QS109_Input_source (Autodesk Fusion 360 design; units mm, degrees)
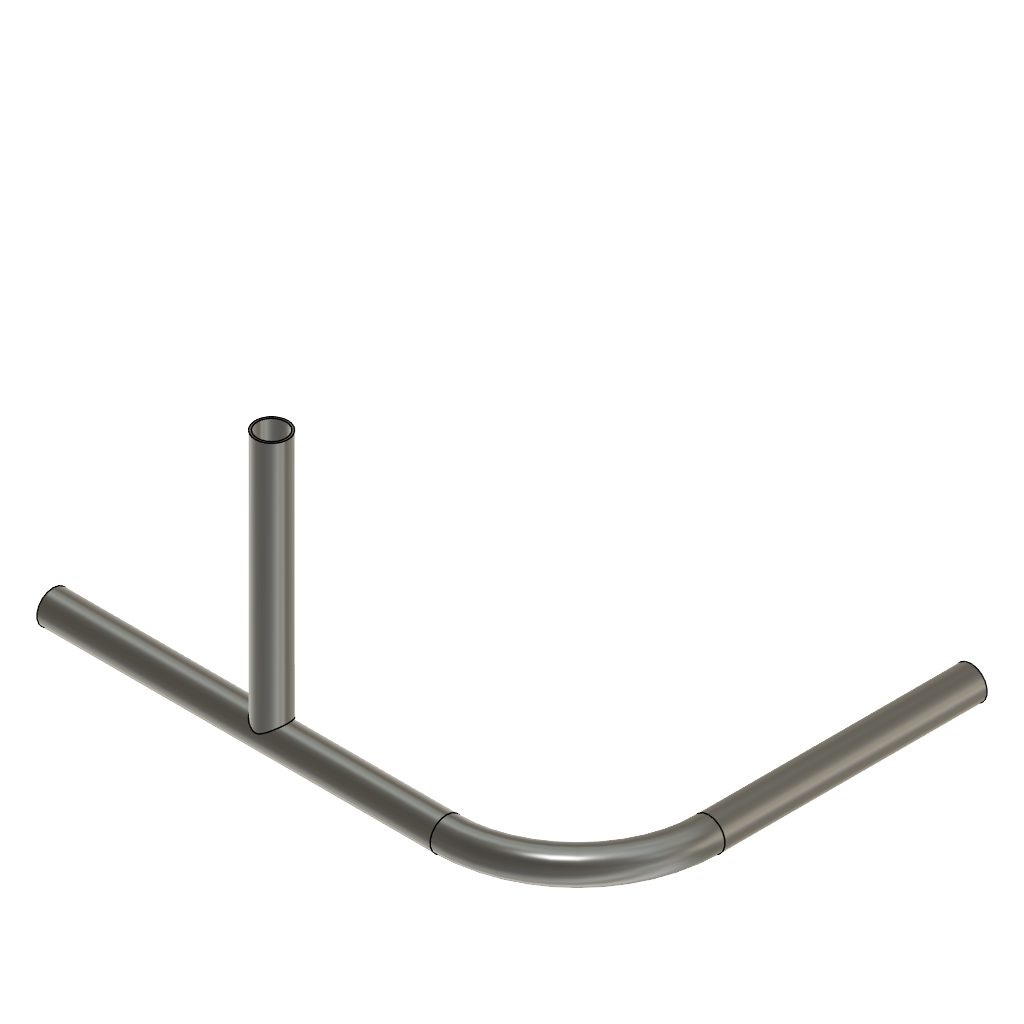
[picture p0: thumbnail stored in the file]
part number: 2026-10-26-11-38-19-526
sketch "tube H1 Bent host" plane through (0, 0, 0) normal (0, 0, 1) x axis (1, 0, 0)
  line L1 (457.2, 0) -> (0, 0)
  line L2 (609.6, 457.2) -> (609.6, 152.4)
  arc A1 centre (457.2, 152.4) radius 152.4 clockwise from (609.6, 152.4) to (457.2, 0)
work_plane "WorkPlane1" ExtraOffset 0
sketch "Sketch2" plane through (0, 0, 0) normal (1, 0, 0) x axis (0, 0, 1)
  circle C1 centre (0, 0) radius 19.05
  circle C2 centre (0, 0) radius 16.637
sweep "Sweep1" sketch "Sketch2" TwistAngle 0 TaperAngle 0 bodies "H1 Bent host"
sketch "tube I1 Imported coped brace" plane through (0, 0, 0) normal (0, 0, 1) x axis (1, 0, 0)
work_plane "WorkPlane2" ExtraOffset 0
sketch "Sketch4" plane through (254, 0, 0) normal (0, 0, 1) x axis (0, 1, 0)
  circle C1 centre (0, 0) radius 19.05
  circle C2 centre (0, 0) radius 16.637
sweep "Sweep2" sketch "Sketch4" TwistAngle 0 TaperAngle 0 bodies "I1 Imported coped brace"
base_feature "Base Feature"
surface_stitch "SurfaceStitch1" StitchingTolerence 0.01 bodies "normcope_I1_Imported_coped_brace_A"
split "Split1" bodies "I1 Imported coped brace"
remove_body "RemoveBody1" bodies "I1 Imported coped brace"
remove_body "RemoveBody2" bodies "I1 Imported coped brace"
named bodies: "H1 Bent host", "I1 Imported coped brace", "normcope_I1_Imported_coped_brace_A"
